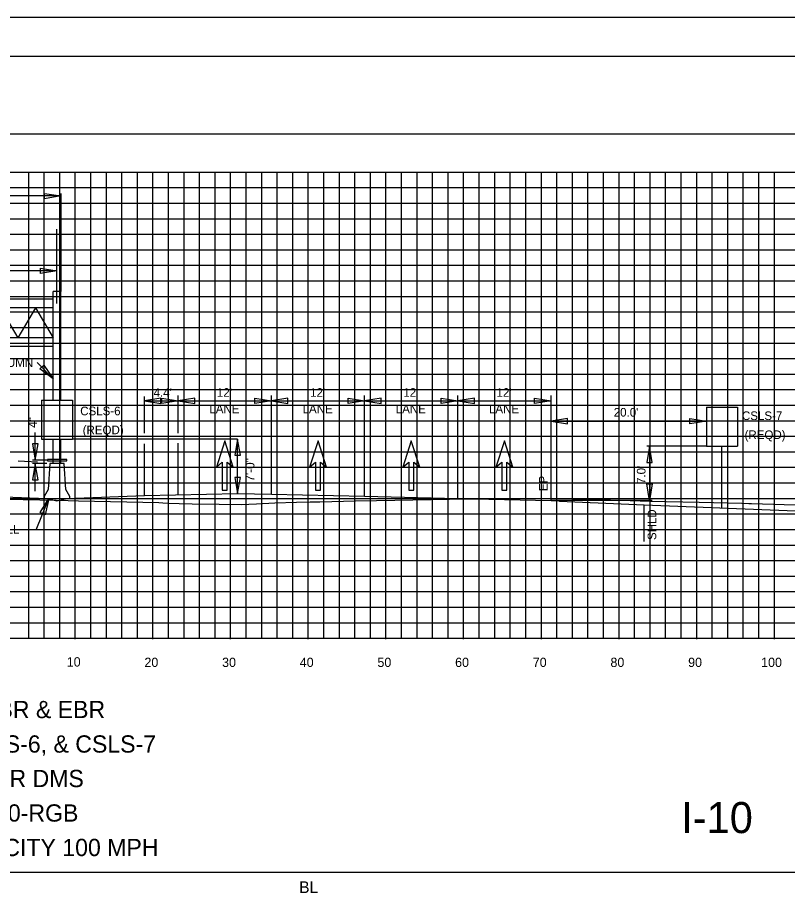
# Model space of a CAD drawing. Extents: x 2193008 to 2198143, y 1236112 to 1237864.
# Drawn here: x 2194690.3 to 2194789.4, y 1237224.5 to 1237338 of the extents above; entities that cross this region are included whole.
import ezdxf

# ---------------------------------------------------------------- set-up
doc = ezdxf.new("R2010")
doc.units = 0
for name, color, linetype in [('10', 7, 'Continuous'), ('3', 7, 'Continuous'), ('60', 7, 'Continuous'), ('CL-CNST', 7, 'Continuous'), ('GSDIMS', 7, 'Continuous'), ('Level 28', 7, 'Continuous'), ('Level 33', 7, 'Continuous'), ('Level 55', 7, 'Continuous'), ('Level 61', 7, 'Continuous'), ('Level 62', 7, 'Continuous'), ('M-ROADS', 7, 'Continuous'), ('SHT-BDR', 7, 'Continuous'), ('SHT-BNDRY', 7, 'Continuous')]:
    doc.layers.add(name, color=color, linetype=linetype)

msp = doc.modelspace()

# ---------------------------------------------------------------- linework, layer by layer
for p, q in [((2194695.33, 1237301.25), (2194695.33, 1237310.79)), ((2194722.94, 1237276.68), (2194722.94, 1237278.68)), ((2194734.94, 1237276.42), (2194734.94, 1237278.42)), ((2194746.94, 1237276.16), (2194746.94, 1237278.16)), ((2194758.94, 1237275.89), (2194758.94, 1237277.89))]:
    msp.add_line(p, q)
msp.add_lwpolyline([(2194697, 1237276.39), (2194696.47, 1237277.3), (2194696.25, 1237280.63), (2194694.42, 1237280.63), (2194694.19, 1237277.3), (2194693.66, 1237276.39), (2194693.66, 1237276.13), (2194697, 1237276.13)], close=True)
at = {"layer": '3'}
for p, q in [((2194695.83, 1237315.08), (2194604.45, 1237315.08)), ((2194695.83, 1237315.42), (2194695.83, 1237302.78)), ((2194694.83, 1237288.78), (2194694.83, 1237302.78)), ((2194695.83, 1237288.78), (2194695.83, 1237302.78)), ((2194694.83, 1237291.54), (2194692.8, 1237293.63)), ((2194706.58, 1237284.54), (2194706.58, 1237289.29)), ((2194710.94, 1237284.54), (2194710.94, 1237289.39)), ((2194722.94, 1237276.68), (2194722.94, 1237289.39)), ((2194734.94, 1237276.42), (2194734.94, 1237289.39)), ((2194746.94, 1237276.16), (2194746.94, 1237289.39)), ((2194758.94, 1237275.89), (2194758.94, 1237289.39)), ((2194692.54, 1237281.08), (2194692.54, 1237284.63)), ((2194694.83, 1237280.63), (2194694.83, 1237283.78)), ((2194695.83, 1237280.63), (2194695.83, 1237283.78)), ((2194706.58, 1237276.52), (2194706.58, 1237283.19)), ((2194710.94, 1237276.61), (2194710.94, 1237283.28)), ((2194718.59, 1237276.78), (2194718.59, 1237283.78)), ((2194780.94, 1237274.94), (2194780.94, 1237282.89)), ((2194690.35, 1237280.97), (2194692.81, 1237280.84)), ((2194694.01, 1237281.08), (2194692.19, 1237281.08)), ((2194694.01, 1237280.63), (2194692.19, 1237280.63)), ((2194692.54, 1237277.08), (2194692.54, 1237280.63)), ((2194692.64, 1237272.11), (2194694.29, 1237276.13)), ((2194537.69, 1237228.05), (2194837.69, 1237228.05))]:
    msp.add_line(p, q, dxfattribs=at)
msp.add_lwpolyline([(2194694.12, 1237280.99), (2194696.59, 1237280.99), (2194696.59, 1237281.17), (2194694.12, 1237281.17)], close=True, dxfattribs=at)
at = {"layer": '60'}
for p, q in [((2194817.69, 1237258.11), (2194557.69, 1237258.11)), ((2194697.69, 1237258.05), (2194697.69, 1237258.11)), ((2194707.69, 1237258.05), (2194707.69, 1237258.11)), ((2194707.69, 1237258.05), (2194707.69, 1237258.11)), ((2194717.69, 1237258.05), (2194717.69, 1237258.11)), ((2194727.69, 1237258.05), (2194727.69, 1237258.11)), ((2194737.69, 1237258.05), (2194737.69, 1237258.11)), ((2194747.69, 1237258.05), (2194747.69, 1237258.11)), ((2194757.69, 1237258.05), (2194757.69, 1237258.11)), ((2194767.69, 1237258.05), (2194767.69, 1237258.11)), ((2194777.69, 1237258.05), (2194777.69, 1237258.11)), ((2194787.69, 1237258.05), (2194787.69, 1237258.11)), ((2194787.75, 1237258.11), (2194787.69, 1237258.11))]:
    msp.add_line(p, q, dxfattribs=at)
at = {"layer": 'CL-CNST'}
msp.add_lwpolyline([(2194684.08, 1237276.52), (2194694.08, 1237276.12), (2194695.33, 1237275.85), (2194695.33, 1237275.85), (2194696.58, 1237276.12), (2194706.58, 1237276.52), (2194718.59, 1237276.78), (2194722.94, 1237276.68), (2194734.94, 1237276.42), (2194746.94, 1237276.16), (2194758.94, 1237275.89), (2194759.93, 1237275.85), (2194760.01, 1237275.78), (2194768.94, 1237275.42), (2194770.94, 1237275.34), (2194804.49, 1237274)], dxfattribs=at)
at = {"layer": 'GSDIMS'}
for p, q in [((2194695.33, 1237305.44), (2194674.62, 1237305.44)), ((2194695.83, 1237302.78), (2194694.83, 1237302.78)), ((2194694.83, 1237301.78), (2194674.62, 1237301.78)), ((2194694.83, 1237300.67), (2194674.62, 1237300.67)), ((2194688, 1237300.67), (2194690.28, 1237296.81)), ((2194692.56, 1237300.67), (2194690.28, 1237296.81)), ((2194692.56, 1237300.67), (2194694.83, 1237296.81)), ((2194694.83, 1237296.81), (2194674.62, 1237296.81)), ((2194694.83, 1237295.7), (2194674.62, 1237295.7)), ((2194693.33, 1237288.78), (2194697.33, 1237288.78)), ((2194693.33, 1237288.78), (2194693.33, 1237283.78)), ((2194697.33, 1237288.78), (2194697.33, 1237283.78)), ((2194706.58, 1237288.73), (2194710.94, 1237288.73)), ((2194710.94, 1237288.73), (2194722.94, 1237288.73)), ((2194722.94, 1237288.73), (2194734.94, 1237288.73)), ((2194734.94, 1237288.73), (2194746.94, 1237288.73)), ((2194746.94, 1237288.73), (2194758.94, 1237288.73)), ((2194778.94, 1237287.89), (2194778.94, 1237282.89)), ((2194778.94, 1237287.89), (2194782.94, 1237287.89)), ((2194782.94, 1237287.89), (2194782.94, 1237282.89)), ((2194693.33, 1237283.78), (2194697.33, 1237283.78)), ((2194718.59, 1237283.78), (2194697.33, 1237283.78)), ((2194778.94, 1237282.89), (2194771.26, 1237282.89)), ((2194771.6, 1237282.89), (2194771.6, 1237275.89)), ((2194778.94, 1237282.89), (2194782.94, 1237282.89)), ((2194771.95, 1237275.89), (2194758.94, 1237275.89)), ((2194770.94, 1237270.62), (2194770.94, 1237275.34))]:
    msp.add_line(p, q, dxfattribs=at)
for points in [[(2194695.83, 1237315.08), (2194693.71, 1237314.73), (2194693.71, 1237315.42)], [(2194695.33, 1237305.44), (2194693.21, 1237305.1), (2194693.21, 1237305.79)], [(2194694.83, 1237291.54), (2194693.11, 1237292.81), (2194693.63, 1237293.29)], [(2194706.58, 1237288.73), (2194708.71, 1237288.38), (2194708.71, 1237289.07)], [(2194710.94, 1237288.73), (2194708.81, 1237288.38), (2194708.81, 1237289.07)], [(2194710.94, 1237288.73), (2194713.07, 1237288.38), (2194713.07, 1237289.07)], [(2194722.94, 1237288.73), (2194720.81, 1237288.38), (2194720.81, 1237289.07)], [(2194722.94, 1237288.73), (2194725.07, 1237288.38), (2194725.07, 1237289.07)], [(2194734.94, 1237288.73), (2194732.81, 1237288.38), (2194732.81, 1237289.07)], [(2194734.94, 1237288.73), (2194737.07, 1237288.38), (2194737.07, 1237289.07)], [(2194746.94, 1237288.73), (2194744.81, 1237288.38), (2194744.81, 1237289.07)], [(2194746.94, 1237288.73), (2194749.07, 1237288.38), (2194749.07, 1237289.07)], [(2194758.94, 1237288.73), (2194756.81, 1237288.38), (2194756.81, 1237289.07)], [(2194758.94, 1237286.09), (2194761.07, 1237285.74), (2194761.07, 1237286.44)], [(2194778.94, 1237286.09), (2194776.81, 1237285.74), (2194776.81, 1237286.44)], [(2194692.54, 1237281.08), (2194692.9, 1237283.16), (2194692.19, 1237283.16)], [(2194718.59, 1237283.78), (2194718.23, 1237281.7), (2194718.94, 1237281.7)], [(2194771.6, 1237282.89), (2194771.26, 1237280.76), (2194771.95, 1237280.76)], [(2194692.54, 1237280.63), (2194692.19, 1237278.55), (2194692.9, 1237278.55)], [(2194718.59, 1237276.78), (2194718.94, 1237278.86), (2194718.23, 1237278.86)], [(2194771.6, 1237275.89), (2194771.26, 1237278.02), (2194771.95, 1237278.02)], [(2194694.29, 1237276.13), (2194693.81, 1237274.05), (2194693.17, 1237274.33)]]:
    msp.add_lwpolyline(points, close=True, dxfattribs=at)
at = {"layer": 'Level 28'}
for p, q in [((2194716.94, 1237283.56), (2194715.85, 1237280.16)), ((2194718.03, 1237280.16), (2194716.94, 1237283.56)), ((2194728.94, 1237283.56), (2194727.85, 1237280.16)), ((2194730.03, 1237280.16), (2194728.94, 1237283.56)), ((2194740.94, 1237283.56), (2194739.85, 1237280.16)), ((2194742.03, 1237280.16), (2194740.94, 1237283.56)), ((2194752.94, 1237283.56), (2194751.85, 1237280.16)), ((2194754.03, 1237280.16), (2194752.94, 1237283.56)), ((2194715.85, 1237280.16), (2194716.61, 1237280.8)), ((2194716.61, 1237280.8), (2194716.61, 1237277.23)), ((2194717.26, 1237277.23), (2194717.26, 1237280.8)), ((2194717.26, 1237280.8), (2194718.03, 1237280.16)), ((2194727.85, 1237280.16), (2194728.61, 1237280.8)), ((2194728.61, 1237280.8), (2194728.61, 1237277.23)), ((2194729.26, 1237277.23), (2194729.26, 1237280.8)), ((2194729.26, 1237280.8), (2194730.03, 1237280.16)), ((2194739.85, 1237280.16), (2194740.61, 1237280.8)), ((2194740.61, 1237280.8), (2194740.61, 1237277.23)), ((2194741.26, 1237277.23), (2194741.26, 1237280.8)), ((2194741.26, 1237280.8), (2194742.03, 1237280.16)), ((2194751.85, 1237280.16), (2194752.61, 1237280.8)), ((2194752.61, 1237280.8), (2194752.61, 1237277.23)), ((2194753.26, 1237277.23), (2194753.26, 1237280.8)), ((2194753.26, 1237280.8), (2194754.03, 1237280.16)), ((2194716.61, 1237277.23), (2194717.26, 1237277.23)), ((2194728.61, 1237277.23), (2194729.26, 1237277.23)), ((2194740.61, 1237277.23), (2194741.26, 1237277.23)), ((2194752.61, 1237277.23), (2194753.26, 1237277.23))]:
    msp.add_line(p, q, dxfattribs=at)
at = {"layer": 'Level 61'}
msp.add_line((2194758.94, 1237286.09), (2194778.94, 1237286.09), dxfattribs=at)
at = {"layer": 'Level 62'}
for p, q in [((2194817.69, 1237318.11), (2194557.69, 1237318.11)), ((2194691.69, 1237258.11), (2194691.69, 1237318.11)), ((2194693.69, 1237258.11), (2194693.69, 1237318.11)), ((2194695.69, 1237258.11), (2194695.69, 1237318.11)), ((2194697.69, 1237258.11), (2194697.69, 1237318.11)), ((2194699.69, 1237258.11), (2194699.69, 1237318.11)), ((2194701.69, 1237258.11), (2194701.69, 1237318.11)), ((2194703.69, 1237258.11), (2194703.69, 1237318.11)), ((2194705.69, 1237258.11), (2194705.69, 1237318.11)), ((2194707.69, 1237258.11), (2194707.69, 1237318.11)), ((2194707.69, 1237258.11), (2194707.69, 1237318.11)), ((2194709.69, 1237258.11), (2194709.69, 1237318.11)), ((2194711.69, 1237258.11), (2194711.69, 1237318.11)), ((2194713.69, 1237258.11), (2194713.69, 1237318.11)), ((2194715.69, 1237258.11), (2194715.69, 1237318.11)), ((2194717.69, 1237258.11), (2194717.69, 1237318.11)), ((2194719.69, 1237258.11), (2194719.69, 1237318.11)), ((2194721.69, 1237258.11), (2194721.69, 1237318.11)), ((2194723.69, 1237258.11), (2194723.69, 1237318.11)), ((2194725.69, 1237258.11), (2194725.69, 1237318.11)), ((2194727.69, 1237258.11), (2194727.69, 1237318.11)), ((2194729.69, 1237258.11), (2194729.69, 1237318.11)), ((2194731.69, 1237258.11), (2194731.69, 1237318.11)), ((2194733.69, 1237258.11), (2194733.69, 1237318.11)), ((2194735.69, 1237258.11), (2194735.69, 1237318.11)), ((2194737.69, 1237258.11), (2194737.69, 1237318.11)), ((2194739.69, 1237258.11), (2194739.69, 1237318.11)), ((2194741.69, 1237258.11), (2194741.69, 1237318.11)), ((2194743.69, 1237258.11), (2194743.69, 1237318.11)), ((2194745.69, 1237258.11), (2194745.69, 1237318.11)), ((2194747.69, 1237258.11), (2194747.69, 1237318.11)), ((2194749.69, 1237258.11), (2194749.69, 1237318.11)), ((2194751.69, 1237258.11), (2194751.69, 1237318.11)), ((2194753.69, 1237258.11), (2194753.69, 1237318.11)), ((2194755.69, 1237258.11), (2194755.69, 1237318.11)), ((2194757.69, 1237258.11), (2194757.69, 1237318.11)), ((2194759.69, 1237258.11), (2194759.69, 1237318.11)), ((2194761.69, 1237258.11), (2194761.69, 1237318.11)), ((2194763.69, 1237258.11), (2194763.69, 1237318.11)), ((2194765.69, 1237258.11), (2194765.69, 1237318.11)), ((2194767.69, 1237258.11), (2194767.69, 1237318.11)), ((2194769.69, 1237258.11), (2194769.69, 1237318.11)), ((2194771.69, 1237258.11), (2194771.69, 1237318.11)), ((2194773.69, 1237258.11), (2194773.69, 1237318.11)), ((2194775.69, 1237258.11), (2194775.69, 1237318.11)), ((2194777.69, 1237258.11), (2194777.69, 1237318.11)), ((2194779.69, 1237258.11), (2194779.69, 1237318.11)), ((2194781.69, 1237258.11), (2194781.69, 1237318.11)), ((2194783.69, 1237258.11), (2194783.69, 1237318.11)), ((2194785.69, 1237258.11), (2194785.69, 1237318.11)), ((2194787.69, 1237258.11), (2194787.69, 1237318.11)), ((2194817.69, 1237316.11), (2194557.69, 1237316.11)), ((2194817.69, 1237314.11), (2194557.69, 1237314.11)), ((2194817.69, 1237312.11), (2194557.69, 1237312.11)), ((2194817.69, 1237310.11), (2194557.69, 1237310.11)), ((2194817.69, 1237308.11), (2194557.69, 1237308.11)), ((2194817.69, 1237306.11), (2194557.69, 1237306.11)), ((2194817.69, 1237304.11), (2194557.69, 1237304.11)), ((2194817.69, 1237302.11), (2194557.69, 1237302.11)), ((2194817.69, 1237300.11), (2194557.69, 1237300.11)), ((2194817.69, 1237298.11), (2194557.69, 1237298.11)), ((2194817.69, 1237296.11), (2194557.69, 1237296.11)), ((2194817.69, 1237294.11), (2194557.69, 1237294.11)), ((2194817.69, 1237292.11), (2194557.69, 1237292.11)), ((2194817.69, 1237290.11), (2194557.69, 1237290.11)), ((2194817.69, 1237288.11), (2194557.69, 1237288.11)), ((2194817.69, 1237286.11), (2194557.69, 1237286.11)), ((2194817.69, 1237284.11), (2194557.69, 1237284.11)), ((2194817.69, 1237282.11), (2194557.69, 1237282.11)), ((2194817.69, 1237280.11), (2194557.69, 1237280.11)), ((2194817.69, 1237278.11), (2194557.69, 1237278.11)), ((2194817.69, 1237276.11), (2194557.69, 1237276.11)), ((2194817.69, 1237274.11), (2194557.69, 1237274.11)), ((2194817.69, 1237272.11), (2194557.69, 1237272.11)), ((2194817.69, 1237270.11), (2194557.69, 1237270.11)), ((2194817.69, 1237268.11), (2194557.69, 1237268.11)), ((2194817.69, 1237266.11), (2194557.69, 1237266.11)), ((2194817.69, 1237264.11), (2194557.69, 1237264.11)), ((2194817.69, 1237262.11), (2194557.69, 1237262.11)), ((2194817.69, 1237260.11), (2194557.69, 1237260.11)), ((2194817.69, 1237258.11), (2194557.69, 1237258.11))]:
    msp.add_line(p, q, dxfattribs=at)
msp.add_lwpolyline([(2194512.69, 1237118.04), (2194852.69, 1237118.04), (2194852.69, 1237338.04), (2194512.69, 1237338.04)], close=True, dxfattribs=at)
at = {"layer": 'M-ROADS'}
msp.add_lwpolyline([(2194684.58, 1237276.15), (2194695.23, 1237275.93), (2194696.79, 1237275.9), (2194698.1, 1237275.86), (2194708.46, 1237275.62), (2194708.95, 1237275.59), (2194709.7, 1237275.56), (2194711.05, 1237275.51), (2194712.72, 1237275.44), (2194716.23, 1237275.4), (2194719.04, 1237275.36), (2194721, 1237275.46), (2194723.37, 1237275.57), (2194726.15, 1237275.65), (2194727.91, 1237275.7), (2194728.78, 1237275.72), (2194729.16, 1237275.73), (2194733.77, 1237275.83), (2194736.45, 1237275.88), (2194743.52, 1237276), (2194748.22, 1237276.08), (2194750.24, 1237276.08), (2194760.22, 1237276.12), (2194766.59, 1237275.95), (2194771.68, 1237275.81), (2194778.02, 1237275.67), (2194783.52, 1237275.54), (2194784.42, 1237275.5), (2194784.76, 1237275.48), (2194791.77, 1237275.28)], dxfattribs=at)
at = {"layer": 'SHT-BDR'}
msp.add_lwpolyline([(2194537.69, 1237133.05), (2194837.69, 1237133.05), (2194837.69, 1237323.05), (2194537.69, 1237323.05)], close=True, dxfattribs=at)
at = {"layer": 'SHT-BNDRY'}
msp.add_lwpolyline([(2194525.19, 1237123.04), (2194847.69, 1237123.04), (2194847.69, 1237333.04), (2194525.19, 1237333.04)], close=True, dxfattribs=at)

# ---------------------------------------------------------------- texts
at = {"layer": '10'}
for s, p in [('10', (2194696.59, 1237254.51)), ('20', (2194706.59, 1237254.45)), ('30', (2194716.59, 1237254.45)), ('40', (2194726.59, 1237254.45)), ('50', (2194736.59, 1237254.45)), ('60', (2194746.59, 1237254.45)), ('70', (2194756.59, 1237254.45)), ('80', (2194766.59, 1237254.45)), ('90', (2194776.59, 1237254.45)), ('100', (2194785.99, 1237254.45))]:
    msp.add_text(s, height=1.2, dxfattribs=at).set_placement(p)
at = {"layer": '60'}
msp.add_text('BL', height=1.5, dxfattribs=at).set_placement((2194726.51, 1237225.36))
at = {"layer": 'Level 33'}
msp.add_text('I-10', height=3.998, rotation=360, dxfattribs=at).set_placement((2194775.71, 1237233.07))
at = {"layer": 'Level 55'}
for s, height, rotation, p in [('COLUMN', 1.11, 360, (2194685.83, 1237293.08)), ('CSLS-6', 1.11, 360, (2194698.32, 1237286.85)), ('4"', 1.135, 90, (2194692.75, 1237285.24)), ('CSLS-7', 1.11, 360, (2194783.52, 1237286.24)), ('(REQD)', 1.11, 360, (2194698.64, 1237284.41)), ('(REQD)', 1.11, 360, (2194783.86, 1237283.79)), ('7\'-0"', 1.135, 90, (2194720.75, 1237278.31)), ("7.0'", 1.11, 90, (2194771.1, 1237278.01)), ('EP', 1.11, 90, (2194758.49, 1237277.09)), ('SHLD', 1.11, 90, (2194772.49, 1237270.79)), ('CONC BAR WALL', 1.1105, 360, (2194678.21, 1237271.62))]:
    msp.add_text(s, height=height, rotation=rotation, dxfattribs=at).set_placement(p)
for s, height, p in [("4.4'", 1.11, (2194707.77, 1237289.23)), ("12'", 1.11, (2194715.92, 1237289.23)), ("12'", 1.11, (2194727.92, 1237289.23)), ("12'", 1.11, (2194739.92, 1237289.23)), ("12'", 1.11, (2194751.92, 1237289.23)), ('LANE', 1.11, (2194714.95, 1237287.12)), ('LANE', 1.11, (2194726.95, 1237287.12)), ('LANE', 1.11, (2194738.95, 1237287.12)), ('LANE', 1.11, (2194750.95, 1237287.12)), ("20.0'", 1.11, (2194767.01, 1237286.68)), ('I-10 STA. 125+00 WBR & EBR', 2.2209, (2194660.68, 1237247.87)), ('REQD OHSB-10, OHV-5, CSLS-6, & CSLS-7', 2.2209, (2194648.34, 1237243.43)), ('FULL-COLOR DMS', 2.2209, (2194672.55, 1237238.99)), ('VF-2020-96x400-20-RGB', 2.2209, (2194664.25, 1237234.55)), ('DESIGN WIND VELOCITY 100 MPH', 2.2209, (2194659.55, 1237230.11))]:
    msp.add_text(s, height=height, dxfattribs=at).set_placement(p)

doc.saveas('drawing.dxf')
